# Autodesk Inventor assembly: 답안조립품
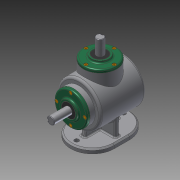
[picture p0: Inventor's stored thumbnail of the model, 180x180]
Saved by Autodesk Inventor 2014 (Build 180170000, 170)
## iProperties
Created: 2016-04
Part Number: 답안조립품
Document SubType Name: Assembly
Designer: owner
Author: owner
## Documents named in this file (14)
- C:\Users\owner\Desktop\460407V1003\답안조립품.iam
- C:\Users\owner\Desktop\460407V1003\1-본체.ipt
- C:\Users\owner\Desktop\460407V1003\커버.ipt
- C:\Users\owner\Desktop\460407V1003\베어링 6203.ipt
- C:\Users\owner\Desktop\460407V1003\메인 축.ipt
- 메인 축.ipt
- C:\Users\owner\Desktop\460407V1003\키 5x5.ipt
- C:\Users\owner\Desktop\460407V1003\메인 베벨기어.ipt
- C:\Users\owner\Desktop\460407V1003\서브 축.ipt
- 서브 축.ipt
- C:\Users\owner\Desktop\460407V1003\키 4x4.ipt
- C:\Users\owner\Desktop\460407V1003\서브 베벨기어.ipt
- C:\Users\owner\Desktop\460407V1003\오일실 17 32 8.ipt
- C:\Users\owner\Desktop\460407V1003\M4.ipt
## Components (9 placed, 2 different names)
1. 1-본체:1
2. M4:2
3. M4:3
4. M4:4
5. M4:5
6. M4:1
7. M4:6
8. M4:7
9. M4:8
